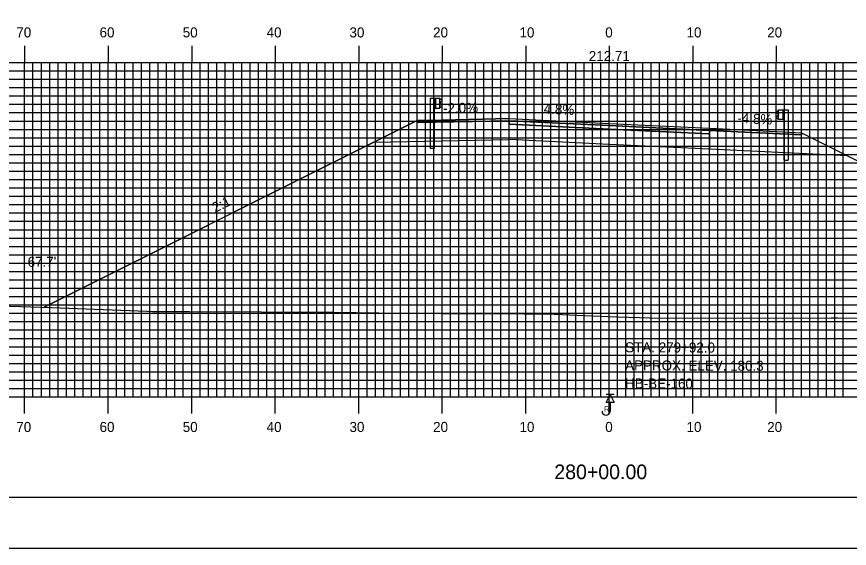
# Model space of a CAD drawing. Extents: x 1810980 to 1811323, y 442591 to 442811.
# Drawn here: x 1811074.9 to 1811174.6, y 442590.5 to 442654.1 of the extents above; entities that cross this region are included whole.
import ezdxf

# ---------------------------------------------------------------- set-up
doc = ezdxf.new("R2010")
doc.units = 0
for name, color, linetype in [('ANNOTATION', 7, 'Continuous'), ('BORDER', 7, 'Continuous'), ('BORING - REFUSAL', 7, 'Continuous'), ('D_Guardrail_Beam_Lt', 7, 'Continuous'), ('D_Guardrail_Beam_Rt', 7, 'Continuous'), ('D_Roadway_Centerline', 7, 'Continuous'), ('D_Roadway_Centerline_Text', 7, 'Continuous'), ('D_Roadway_Edge_Shoulder', 7, 'Continuous'), ('D_Roadway_Edge_TW', 7, 'Continuous'), ('D_Roadway_Pavement', 7, 'Continuous'), ('D_Roadway_SlopeLines', 7, 'Continuous'), ('D_Roadway_SubGrade', 7, 'Continuous'), ('D_Text_Standard', 7, 'Continuous'), ('H_V ANNOTATION', 7, 'Continuous'), ('MAJOR', 7, 'Continuous'), ('MINOR', 7, 'Continuous'), ('PLOT BOUNDARY', 7, 'Continuous'), ('S_Roadway_Centerline', 7, 'Continuous')]:
    doc.layers.add(name, color=color, linetype=linetype)

msp = doc.modelspace()

# ---------------------------------------------------------------- linework, layer by layer
at = {"layer": 'BORDER'}
msp.add_lwpolyline([(1810996.29, 442596.665), (1811316.29, 442596.665), (1811316.29, 442806.665), (1810996.29, 442806.665)], close=True, dxfattribs=at)
at = {"layer": 'BORING - REFUSAL'}
for p, q in [((1811146.469, 442608.965), (1811145.51, 442608.965)), ((1811145.99, 442608.006), (1811145.99, 442606.947))]:
    msp.add_line(p, q, dxfattribs=at)
msp.add_lwpolyline([(1811145.99, 442608.965), (1811146.469, 442608.006), (1811145.51, 442608.006)], close=True, dxfattribs=at)
msp.add_arc((1811145.505, 442606.947), 0.485, 180, 0, dxfattribs=at)
at = {"layer": 'D_Guardrail_Beam_Lt'}
for p, q in [((1811124.461, 442644.37), (1811124.461, 442638.37)), ((1811124.931, 442644.37), (1811124.461, 442644.37)), ((1811125.619, 442644.37), (1811124.931, 442644.37)), ((1811124.931, 442644.37), (1811124.931, 442643.203)), ((1811124.994, 442644.37), (1811124.994, 442643.203)), ((1811125.098, 442644.37), (1811125.098, 442643.203)), ((1811125.619, 442643.203), (1811125.619, 442644.37)), ((1811125.619, 442644.286), (1811125.693, 442644.272)), ((1811125.852, 442644.022), (1811125.657, 442643.886)), ((1811125.709, 442644.265), (1811125.852, 442644.165)), ((1811124.931, 442643.203), (1811125.619, 442643.203)), ((1811124.952, 442638.37), (1811124.952, 442643.203)), ((1811125.693, 442643.301), (1811125.619, 442643.286)), ((1811125.623, 442643.821), (1811125.623, 442643.751)), ((1811125.657, 442643.687), (1811125.852, 442643.551)), ((1811125.852, 442643.407), (1811125.709, 442643.307)), ((1811124.952, 442638.37), (1811124.461, 442638.37))]:
    msp.add_line(p, q, dxfattribs=at)
for centre, major_axis, start_param, end_param in [((1811125.685, 442644.231), (0.0417, 0), 0.959931, 1.376053), ((1811125.802, 442644.093), (0.0877, 0), 5.323254, 7.243116), ((1811125.702, 442643.821), (-0.0789, 0), 5.323254, 6.283185), ((1811125.702, 442643.751), (-0.0789, 0), 6.283185, 7.243116), ((1811125.685, 442643.341), (0.0417, 0), 4.907132, 5.323254), ((1811125.802, 442643.479), (0.0877, 0), 5.323254, 7.243116)]:
    msp.add_ellipse(centre, major_axis=major_axis, ratio=0.995501, start_param=start_param, end_param=end_param, dxfattribs=at)
at = {"layer": 'D_Guardrail_Beam_Rt'}
for p, q in [((1811166.161, 442642.91), (1811166.086, 442642.896)), ((1811166.161, 442642.994), (1811166.848, 442642.994)), ((1811166.161, 442641.827), (1811166.161, 442642.994)), ((1811166.681, 442642.994), (1811166.681, 442641.827)), ((1811166.786, 442642.994), (1811166.786, 442641.827)), ((1811166.848, 442642.994), (1811167.319, 442642.994)), ((1811166.848, 442642.994), (1811166.848, 442641.827)), ((1811167.319, 442642.994), (1811167.319, 442636.994)), ((1811166.071, 442642.889), (1811165.927, 442642.789)), ((1811165.927, 442642.646), (1811166.122, 442642.51)), ((1811166.122, 442642.311), (1811165.927, 442642.175)), ((1811165.927, 442642.031), (1811166.071, 442641.931)), ((1811166.086, 442641.925), (1811166.161, 442641.91)), ((1811166.156, 442642.445), (1811166.156, 442642.375)), ((1811166.848, 442641.827), (1811166.161, 442641.827)), ((1811166.827, 442636.994), (1811166.827, 442641.827)), ((1811166.827, 442636.994), (1811167.319, 442636.994))]:
    msp.add_line(p, q, dxfattribs=at)
for centre, major_axis, start_param, end_param in [((1811165.977, 442642.717), (-0.0877, 0), 5.323254, 7.243116), ((1811165.977, 442642.103), (-0.0877, 0), 5.323254, 7.243116), ((1811166.094, 442642.855), (-0.0417, 0), 4.907132, 5.323254), ((1811166.094, 442641.965), (-0.0417, 0), 0.959931, 1.376053), ((1811166.077, 442642.445), (0.0789, 0), 0, 0.959931), ((1811166.077, 442642.375), (0.0789, 0), 5.323254, 6.283185)]:
    msp.add_ellipse(centre, major_axis=major_axis, ratio=0.995501, start_param=start_param, end_param=end_param, dxfattribs=at)
at = {"layer": 'D_Roadway_Centerline'}
msp.add_lwpolyline([(1811078.215, 442619.389), (1811117.681, 442639.122), (1811122.89, 442641.726), (1811125.89, 442641.786), (1811133.89, 442641.946), (1811145.89, 442641.37), (1811157.89, 442640.794), (1811165.89, 442640.41), (1811168.89, 442640.266), (1811174.421, 442637.501), (1811214.762, 442617.33)], dxfattribs=at)
at = {"layer": 'D_Roadway_Edge_Shoulder'}
for points in [[(1811133.89, 442641.946), (1811125.89, 442641.786), (1811125.89, 442641.786), (1811122.89, 442641.726), (1811122.89, 442641.476), (1811133.89, 442641.696)], [(1811157.89, 442640.794), (1811165.89, 442640.41), (1811165.89, 442640.41), (1811168.89, 442640.266), (1811168.89, 442640.016), (1811157.89, 442640.544)]]:
    msp.add_lwpolyline(points, close=True, dxfattribs=at)
at = {"layer": 'D_Roadway_Edge_TW'}
msp.add_lwpolyline([(1811133.89, 442641.696), (1811133.89, 442641.946), (1811145.89, 442641.37), (1811157.89, 442640.794), (1811157.89, 442640.544), (1811145.89, 442641.12)], close=True, dxfattribs=at)
at = {"layer": 'D_Roadway_Pavement'}
msp.add_lwpolyline([(1811133.89, 442641.28), (1811133.89, 442641.696), (1811145.89, 442641.12), (1811157.89, 442640.544), (1811157.89, 442640.128), (1811145.89, 442640.704)], close=True, dxfattribs=at)
for points in [[(1811133.89, 442641.696), (1811133.89, 442641.28)], [(1811157.89, 442640.544), (1811157.89, 442640.128)]]:
    msp.add_lwpolyline(points, dxfattribs=at)
at = {"layer": 'D_Roadway_SlopeLines'}
for points in [[(1811122.89, 442641.726), (1811078.215, 442619.389)], [(1811168.89, 442640.266), (1811214.762, 442617.33)]]:
    msp.add_lwpolyline(points, dxfattribs=at)
at = {"layer": 'D_Roadway_SubGrade'}
for points in [[(1811133.89, 442641.28), (1811133.89, 442641.696), (1811122.89, 442641.476), (1811122.89, 442641.726), (1811117.681, 442639.122), (1811133.89, 442639.446)], [(1811133.89, 442639.446), (1811133.89, 442641.696), (1811133.89, 442641.28), (1811145.89, 442640.704), (1811157.89, 442640.128), (1811157.89, 442640.544), (1811157.89, 442638.294), (1811145.89, 442638.87)], [(1811157.89, 442640.128), (1811157.89, 442640.544), (1811168.89, 442640.016), (1811168.89, 442640.266), (1811174.421, 442637.501), (1811157.89, 442638.294)]]:
    msp.add_lwpolyline(points, close=True, dxfattribs=at)
at = {"layer": 'MAJOR'}
for p, q in [((1811075.89, 442650.669), (1811075.89, 442648.665)), ((1811085.89, 442650.669), (1811085.89, 442648.665)), ((1811095.89, 442650.669), (1811095.89, 442648.665)), ((1811105.89, 442650.669), (1811105.89, 442648.665)), ((1811115.89, 442650.669), (1811115.89, 442648.665)), ((1811125.89, 442650.669), (1811125.89, 442648.665)), ((1811135.89, 442650.669), (1811135.89, 442648.665)), ((1811145.89, 442650.669), (1811145.89, 442648.665)), ((1811155.89, 442650.669), (1811155.89, 442648.665)), ((1811165.89, 442650.669), (1811165.89, 442648.665)), ((1811005.89, 442648.665), (1811285.89, 442648.665)), ((1811005.89, 442648.665), (1811285.89, 442648.665)), ((1811075.89, 442608.665), (1811075.89, 442648.665)), ((1811085.89, 442608.665), (1811085.89, 442648.665)), ((1811095.89, 442608.665), (1811095.89, 442648.665)), ((1811105.89, 442608.665), (1811105.89, 442648.665)), ((1811115.89, 442608.665), (1811115.89, 442648.665)), ((1811125.89, 442608.665), (1811125.89, 442648.665)), ((1811135.89, 442608.665), (1811135.89, 442648.665)), ((1811145.89, 442608.665), (1811145.89, 442648.665)), ((1811155.89, 442608.665), (1811155.89, 442648.665)), ((1811165.89, 442608.665), (1811165.89, 442648.665)), ((1811005.89, 442643.665), (1811285.89, 442643.665)), ((1811005.89, 442638.665), (1811285.89, 442638.665)), ((1811005.89, 442633.665), (1811285.89, 442633.665)), ((1811005.89, 442628.665), (1811285.89, 442628.665)), ((1811005.89, 442623.665), (1811285.89, 442623.665)), ((1811005.89, 442618.665), (1811285.89, 442618.665)), ((1811005.89, 442613.665), (1811285.89, 442613.665)), ((1811005.89, 442608.665), (1811285.89, 442608.665)), ((1811005.89, 442608.665), (1811285.89, 442608.665)), ((1811075.89, 442606.661), (1811075.89, 442608.665)), ((1811085.89, 442606.661), (1811085.89, 442608.665)), ((1811095.89, 442606.661), (1811095.89, 442608.665)), ((1811105.89, 442606.661), (1811105.89, 442608.665)), ((1811115.89, 442606.661), (1811115.89, 442608.665)), ((1811125.89, 442606.661), (1811125.89, 442608.665)), ((1811135.89, 442606.661), (1811135.89, 442608.665)), ((1811145.89, 442606.661), (1811145.89, 442608.665)), ((1811155.89, 442606.661), (1811155.89, 442608.665)), ((1811165.89, 442606.661), (1811165.89, 442608.665))]:
    msp.add_line(p, q, dxfattribs=at)
at = {"layer": 'MINOR'}
for p, q in [((1811076.89, 442608.665), (1811076.89, 442648.665)), ((1811077.89, 442608.665), (1811077.89, 442648.665)), ((1811078.89, 442608.665), (1811078.89, 442648.665)), ((1811079.89, 442608.665), (1811079.89, 442648.665)), ((1811080.89, 442608.665), (1811080.89, 442648.665)), ((1811081.89, 442608.665), (1811081.89, 442648.665)), ((1811082.89, 442608.665), (1811082.89, 442648.665)), ((1811083.89, 442608.665), (1811083.89, 442648.665)), ((1811084.89, 442608.665), (1811084.89, 442648.665)), ((1811086.89, 442608.665), (1811086.89, 442648.665)), ((1811087.89, 442608.665), (1811087.89, 442648.665)), ((1811088.89, 442608.665), (1811088.89, 442648.665)), ((1811089.89, 442608.665), (1811089.89, 442648.665)), ((1811090.89, 442608.665), (1811090.89, 442648.665)), ((1811091.89, 442608.665), (1811091.89, 442648.665)), ((1811092.89, 442608.665), (1811092.89, 442648.665)), ((1811093.89, 442608.665), (1811093.89, 442648.665)), ((1811094.89, 442608.665), (1811094.89, 442648.665)), ((1811096.89, 442608.665), (1811096.89, 442648.665)), ((1811097.89, 442608.665), (1811097.89, 442648.665)), ((1811098.89, 442608.665), (1811098.89, 442648.665)), ((1811099.89, 442608.665), (1811099.89, 442648.665)), ((1811100.89, 442608.665), (1811100.89, 442648.665)), ((1811101.89, 442608.665), (1811101.89, 442648.665)), ((1811102.89, 442608.665), (1811102.89, 442648.665)), ((1811103.89, 442608.665), (1811103.89, 442648.665)), ((1811104.89, 442608.665), (1811104.89, 442648.665)), ((1811106.89, 442608.665), (1811106.89, 442648.665)), ((1811107.89, 442608.665), (1811107.89, 442648.665)), ((1811108.89, 442608.665), (1811108.89, 442648.665)), ((1811109.89, 442608.665), (1811109.89, 442648.665)), ((1811110.89, 442608.665), (1811110.89, 442648.665)), ((1811111.89, 442608.665), (1811111.89, 442648.665)), ((1811112.89, 442608.665), (1811112.89, 442648.665)), ((1811113.89, 442608.665), (1811113.89, 442648.665)), ((1811114.89, 442608.665), (1811114.89, 442648.665)), ((1811116.89, 442608.665), (1811116.89, 442648.665)), ((1811117.89, 442608.665), (1811117.89, 442648.665)), ((1811118.89, 442608.665), (1811118.89, 442648.665)), ((1811119.89, 442608.665), (1811119.89, 442648.665)), ((1811120.89, 442608.665), (1811120.89, 442648.665)), ((1811121.89, 442608.665), (1811121.89, 442648.665)), ((1811122.89, 442608.665), (1811122.89, 442648.665)), ((1811123.89, 442608.665), (1811123.89, 442648.665)), ((1811124.89, 442608.665), (1811124.89, 442648.665)), ((1811126.89, 442608.665), (1811126.89, 442648.665)), ((1811127.89, 442608.665), (1811127.89, 442648.665)), ((1811128.89, 442608.665), (1811128.89, 442648.665)), ((1811129.89, 442608.665), (1811129.89, 442648.665)), ((1811130.89, 442608.665), (1811130.89, 442648.665)), ((1811131.89, 442608.665), (1811131.89, 442648.665)), ((1811132.89, 442608.665), (1811132.89, 442648.665)), ((1811133.89, 442608.665), (1811133.89, 442648.665)), ((1811134.89, 442608.665), (1811134.89, 442648.665)), ((1811136.89, 442608.665), (1811136.89, 442648.665)), ((1811137.89, 442608.665), (1811137.89, 442648.665)), ((1811138.89, 442608.665), (1811138.89, 442648.665)), ((1811139.89, 442608.665), (1811139.89, 442648.665)), ((1811140.89, 442608.665), (1811140.89, 442648.665)), ((1811141.89, 442608.665), (1811141.89, 442648.665)), ((1811142.89, 442608.665), (1811142.89, 442648.665)), ((1811143.89, 442608.665), (1811143.89, 442648.665)), ((1811144.89, 442608.665), (1811144.89, 442648.665)), ((1811146.89, 442608.665), (1811146.89, 442648.665)), ((1811147.89, 442608.665), (1811147.89, 442648.665)), ((1811148.89, 442608.665), (1811148.89, 442648.665)), ((1811149.89, 442608.665), (1811149.89, 442648.665)), ((1811150.89, 442608.665), (1811150.89, 442648.665)), ((1811151.89, 442608.665), (1811151.89, 442648.665)), ((1811152.89, 442608.665), (1811152.89, 442648.665)), ((1811153.89, 442608.665), (1811153.89, 442648.665)), ((1811154.89, 442608.665), (1811154.89, 442648.665)), ((1811156.89, 442608.665), (1811156.89, 442648.665)), ((1811157.89, 442608.665), (1811157.89, 442648.665)), ((1811158.89, 442608.665), (1811158.89, 442648.665)), ((1811159.89, 442608.665), (1811159.89, 442648.665)), ((1811160.89, 442608.665), (1811160.89, 442648.665)), ((1811161.89, 442608.665), (1811161.89, 442648.665)), ((1811162.89, 442608.665), (1811162.89, 442648.665)), ((1811163.89, 442608.665), (1811163.89, 442648.665)), ((1811164.89, 442608.665), (1811164.89, 442648.665)), ((1811166.89, 442608.665), (1811166.89, 442648.665)), ((1811167.89, 442608.665), (1811167.89, 442648.665)), ((1811168.89, 442608.665), (1811168.89, 442648.665)), ((1811169.89, 442608.665), (1811169.89, 442648.665)), ((1811170.89, 442608.665), (1811170.89, 442648.665)), ((1811171.89, 442608.665), (1811171.89, 442648.665)), ((1811172.89, 442608.665), (1811172.89, 442648.665)), ((1811173.89, 442608.665), (1811173.89, 442648.665)), ((1811005.89, 442647.665), (1811285.89, 442647.665)), ((1811005.89, 442646.665), (1811285.89, 442646.665)), ((1811005.89, 442645.665), (1811285.89, 442645.665)), ((1811005.89, 442644.665), (1811285.89, 442644.665)), ((1811005.89, 442642.665), (1811285.89, 442642.665)), ((1811005.89, 442641.665), (1811285.89, 442641.665)), ((1811005.89, 442640.665), (1811285.89, 442640.665)), ((1811005.89, 442639.665), (1811285.89, 442639.665)), ((1811005.89, 442637.665), (1811285.89, 442637.665)), ((1811005.89, 442636.665), (1811285.89, 442636.665)), ((1811005.89, 442635.665), (1811285.89, 442635.665)), ((1811005.89, 442634.665), (1811285.89, 442634.665)), ((1811005.89, 442632.665), (1811285.89, 442632.665)), ((1811005.89, 442631.665), (1811285.89, 442631.665)), ((1811005.89, 442630.665), (1811285.89, 442630.665)), ((1811005.89, 442629.665), (1811285.89, 442629.665)), ((1811005.89, 442627.665), (1811285.89, 442627.665)), ((1811005.89, 442626.665), (1811285.89, 442626.665)), ((1811005.89, 442625.665), (1811285.89, 442625.665)), ((1811005.89, 442624.665), (1811285.89, 442624.665)), ((1811005.89, 442622.665), (1811285.89, 442622.665)), ((1811005.89, 442621.665), (1811285.89, 442621.665)), ((1811005.89, 442620.665), (1811285.89, 442620.665)), ((1811005.89, 442619.665), (1811285.89, 442619.665)), ((1811005.89, 442617.665), (1811285.89, 442617.665)), ((1811005.89, 442616.665), (1811285.89, 442616.665)), ((1811005.89, 442615.665), (1811285.89, 442615.665)), ((1811005.89, 442614.665), (1811285.89, 442614.665)), ((1811005.89, 442612.665), (1811285.89, 442612.665)), ((1811005.89, 442611.665), (1811285.89, 442611.665)), ((1811005.89, 442610.665), (1811285.89, 442610.665)), ((1811005.89, 442609.665), (1811285.89, 442609.665))]:
    msp.add_line(p, q, dxfattribs=at)
at = {"layer": 'PLOT BOUNDARY'}
msp.add_lwpolyline([(1810980.103, 442590.547), (1811320.103, 442590.547), (1811320.103, 442810.547), (1810980.103, 442810.547)], close=True, dxfattribs=at)
at = {"layer": 'S_Roadway_Centerline'}
msp.add_lwpolyline([(1811071.655, 442619.61), (1811079.122, 442619.359), (1811090.51, 442618.911), (1811091.2, 442618.875), (1811091.679, 442618.879), (1811095.608, 442618.858), (1811112.899, 442618.812), (1811118.311, 442618.736), (1811125.979, 442618.634), (1811132.119, 442618.629), (1811139.29, 442618.571), (1811145.708, 442618.263), (1811151.955, 442618.089), (1811172.459, 442618.117), (1811173.06, 442618.123), (1811173.27, 442618.122), (1811192.613, 442617.865)], dxfattribs=at)

# ---------------------------------------------------------------- texts
at = {"layer": 'ANNOTATION'}
for s, rotation, p in [('-2.0%', 1.14576, (1811125.996, 442642.589)), ('4.8%', 357.25191, (1811138.019, 442642.55)), ('-4.8%', 357.25191, (1811161.198, 442641.438)), ('2:1', 26.56505, (1811098.698, 442630.666))]:
    msp.add_text(s, height=1.2, rotation=rotation, dxfattribs=at).set_placement(p)
at = {"layer": 'BORING - REFUSAL'}
for s, p in [('STA. 279+92.0', (1811147.797, 442613.999)), ('APPROX. ELEV. 180.3', (1811147.79, 442611.839)), ('HB-BE-160', (1811147.783, 442609.679))]:
    msp.add_text(s, height=1.2, rotation=359.81416, dxfattribs=at).set_placement(p)
msp.add_text('R', height=0.64, dxfattribs=at).set_placement((1811145.281, 442606.891))
at = {"layer": 'D_Roadway_Centerline'}
for s, p in [('C', (1811145.884, 442641.37)), ('L', (1811145.89, 442641.363))]:
    msp.add_text(s, height=0.0146, dxfattribs=at).set_placement(p)
at = {"layer": 'D_Roadway_Centerline_Text'}
msp.add_text('212.71', height=1.2, dxfattribs=at).set_placement((1811143.439, 442648.834))
at = {"layer": 'D_Text_Standard'}
msp.add_text("67.7'", height=1.2, dxfattribs=at).set_placement((1811076.248, 442624.224))
at = {"layer": 'H_V ANNOTATION'}
for s, height, p in [('70', 1.2, (1811074.894, 442651.665)), ('60', 1.2, (1811084.862, 442651.665)), ('50', 1.2, (1811094.819, 442651.665)), ('40', 1.2, (1811104.862, 442651.665)), ('30', 1.2, (1811114.787, 442651.665)), ('20', 1.2, (1811124.798, 442651.665)), ('10', 1.2, (1811135.14, 442651.665)), ('0', 1.2, (1811145.408, 442651.665)), ('10', 1.2, (1811155.14, 442651.665)), ('20', 1.2, (1811164.798, 442651.665)), ('70', 1.2, (1811074.894, 442604.465)), ('60', 1.2, (1811084.862, 442604.465)), ('50', 1.2, (1811094.819, 442604.465)), ('40', 1.2, (1811104.862, 442604.465)), ('30', 1.2, (1811114.787, 442604.465)), ('20', 1.2, (1811124.798, 442604.465)), ('10', 1.2, (1811135.14, 442604.465)), ('0', 1.2, (1811145.408, 442604.465)), ('10', 1.2, (1811155.14, 442604.465)), ('20', 1.2, (1811164.798, 442604.465)), ('280+00.00', 1.75, (1811139.304, 442598.821))]:
    msp.add_text(s, height=height, dxfattribs=at).set_placement(p)

doc.saveas('drawing.dxf')
